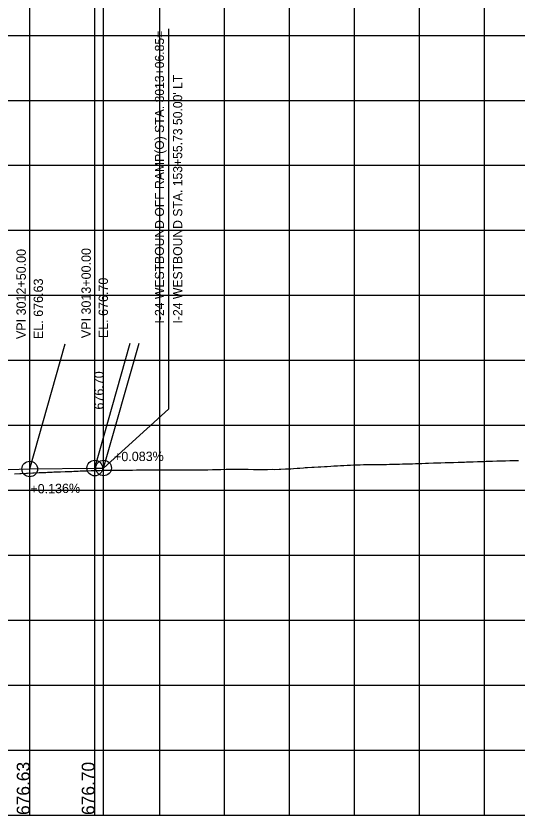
# Model space of a CAD drawing. Extents: x -7164 to 2214450, y -19642 to 253469.
# Drawn here: x 1239 to 1625, y 9000 to 9615 of the extents above; entities that cross this region are included whole.
import ezdxf

# ---------------------------------------------------------------- set-up
doc = ezdxf.new("R2010")
doc.units = 0
for name, color, linetype in [('DESIGN - PROFILE - Proposed', 7, 'Continuous'), ('DESIGN - PROFILE - Proposed Curve Text', 7, 'Continuous'), ('DESIGN - PROFILE - Proposed Text', 7, 'Continuous'), ('DESIGN - SCRATCH - User 1', 7, 'Continuous'), ('DESIGN - SHEET - Light Grid', 7, 'Continuous'), ('SURVEY - PROFILE - Ground Line with Text', 7, 'Continuous')]:
    doc.layers.add(name, color=color, linetype=linetype)

msp = doc.modelspace()

# ---------------------------------------------------------------- linework, layer by layer
at = {"layer": 'DESIGN - PROFILE - Proposed'}
for p, q in [((1250, 9266.3), (1300, 9266.98)), ((1250, 9266.3), (1300, 9266.98)), ((1300, 9266.98), (1306.85, 9267.04)), ((1300, 9266.98), (1306.85, 9267.04)), ((1200, 9265.21), (1250, 9266.3)), ((1200, 9265.21), (1250, 9266.3))]:
    msp.add_line(p, q, dxfattribs=at)
at = {"layer": 'DESIGN - PROFILE - Proposed Text'}
for p, q in [((1356.85, 9604.92), (1356.85, 9377.3)), ((1356.85, 9604.92), (1356.85, 9377.3)), ((1306.85, 9267.04), (1356.85, 9312.3)), ((1306.85, 9267.04), (1356.85, 9312.3))]:
    msp.add_line(p, q, dxfattribs=at)
msp.add_lwpolyline([(1356.85, 9377.3), (1356.85, 9312.3)], dxfattribs=at)
msp.add_lwpolyline([(1356.85, 9377.3), (1356.85, 9312.3)], dxfattribs=at)
for centre in [(1306.85, 9267.04), (1306.85, 9267.04), (1250, 9266.3), (1250, 9266.3), (1300, 9266.98), (1300, 9266.98)]:
    msp.add_circle(centre, 6, dxfattribs=at)
at = {"layer": 'DESIGN - SCRATCH - User 1'}
for p, q in [((1250, 9266.3), (1277.33, 9362.5)), ((1250, 9266.3), (1277.33, 9362.5)), ((1300, 9266.98), (1327.33, 9363.17)), ((1300, 9266.98), (1327.33, 9363.17)), ((1306.85, 9267.04), (1334.18, 9363.23)), ((1306.85, 9267.04), (1334.18, 9363.23)), ((0, 9000), (2600, 9000)), ((0, 9000), (2600, 9000))]:
    msp.add_line(p, q, dxfattribs=at)
msp.add_lwpolyline([(0, 9000), (1306.85, 9000), (1306.85, 10000)], dxfattribs=at)
msp.add_lwpolyline([(0, 9000), (1306.85, 9000), (1306.85, 10000)], dxfattribs=at)
at = {"layer": 'DESIGN - SHEET - Light Grid'}
for p, q in [((1250, 9000), (1250, 10000)), ((1250, 9000), (1250, 10000)), ((1300, 9000), (1300, 10000)), ((1300, 9000), (1300, 10000)), ((1350, 9000), (1350, 10000)), ((1350, 9000), (1350, 10000)), ((1400, 9000), (1400, 10000)), ((1400, 9000), (1400, 10000)), ((1450, 9000), (1450, 10000)), ((1450, 9000), (1450, 10000)), ((1500, 9000), (1500, 10000)), ((1500, 9000), (1500, 10000)), ((1550, 9000), (1550, 10000)), ((1550, 9000), (1550, 10000)), ((1600, 9000), (1600, 10000)), ((1600, 9000), (1600, 10000)), ((0, 9600), (2600, 9600)), ((0, 9600), (2600, 9600)), ((0, 9550), (2600, 9550)), ((0, 9550), (2600, 9550)), ((0, 9500), (2600, 9500)), ((0, 9500), (2600, 9500)), ((0, 9450), (2600, 9450)), ((0, 9450), (2600, 9450)), ((0, 9400), (2600, 9400)), ((0, 9400), (2600, 9400)), ((0, 9350), (2600, 9350)), ((0, 9350), (2600, 9350)), ((0, 9300), (2600, 9300)), ((0, 9300), (2600, 9300)), ((0, 9250), (2600, 9250)), ((0, 9250), (2600, 9250)), ((0, 9200), (2600, 9200)), ((0, 9200), (2600, 9200)), ((0, 9150), (2600, 9150)), ((0, 9150), (2600, 9150)), ((0, 9100), (2600, 9100)), ((0, 9100), (2600, 9100)), ((0, 9050), (2600, 9050)), ((0, 9050), (2600, 9050)), ((0, 9000), (1600, 9000)), ((0, 9000), (1600, 9000))]:
    msp.add_line(p, q, dxfattribs=at)
at = {"layer": 'SURVEY - PROFILE - Ground Line with Text'}
for points in [[(1438.12, 9266.02), (1441.84, 9266.22), (1443.34, 9266.14), (1446.79, 9266.3), (1447.79, 9266.38), (1450.98, 9266.54), (1452.87, 9266.69), (1455.88, 9266.85), (1457.94, 9267.01), (1460.77, 9267.16), (1461.98, 9267.46), (1463.87, 9267.55), (1466.98, 9267.7), (1468.94, 9267.79), (1471.98, 9267.93), (1474.02, 9268.03), (1476.97, 9268.16), (1478.97, 9268.31), (1481.84, 9268.45), (1484.03, 9268.61), (1486.84, 9268.74), (1489.1, 9268.91), (1491.83, 9269.04), (1494.16, 9269.21), (1496.82, 9269.31), (1499.22, 9269.48), (1501.82, 9269.58), (1504.28, 9269.56), (1506.81, 9269.65), (1509.33, 9269.64), (1511.8, 9269.72), (1514.39, 9269.71), (1516.8, 9269.79), (1519.45, 9269.77), (1521.79, 9269.85), (1524.5, 9269.83), (1526.79, 9269.88), (1529.53, 9269.94), (1531.79, 9269.99), (1534.56, 9270.04), (1536.79, 9270.14), (1539.57, 9270.19), (1541.79, 9270.29), (1544.59, 9270.34), (1546.78, 9270.44), (1549.6, 9270.49), (1551.78, 9270.58), (1554.6, 9270.73), (1556.76, 9270.82), (1560.73, 9270.98), (1562.4, 9271.05), (1564.64, 9271.09), (1566.27, 9271.16), (1569.69, 9271.22), (1571.26, 9271.28), (1574.74, 9271.34), (1576.24, 9271.4), (1579.79, 9271.46), (1581.23, 9271.52), (1584.7, 9271.65), (1586.19, 9271.7), (1589.65, 9271.83), (1591.21, 9271.88), (1594.6, 9272), (1596.22, 9272.06), (1599.56, 9272.18), (1601.23, 9272.23), (1604.52, 9272.35), (1606.23, 9272.4), (1609.49, 9272.47), (1611.24, 9272.53), (1614.47, 9272.6), (1616.25, 9272.65), (1619.44, 9272.72), (1621.25, 9272.77), (1624.42, 9272.84), (1626.26, 9272.89)], [(1438.12, 9266.02), (1441.84, 9266.22), (1443.34, 9266.14), (1446.79, 9266.3), (1447.79, 9266.38), (1450.98, 9266.54), (1452.87, 9266.69), (1455.88, 9266.85), (1457.94, 9267.01), (1460.77, 9267.16), (1461.98, 9267.46), (1463.87, 9267.55), (1466.98, 9267.7), (1468.94, 9267.79), (1471.98, 9267.93), (1474.02, 9268.03), (1476.97, 9268.16), (1478.97, 9268.31), (1481.84, 9268.45), (1484.03, 9268.61), (1486.84, 9268.74), (1489.1, 9268.91), (1491.83, 9269.04), (1494.16, 9269.21), (1496.82, 9269.31), (1499.22, 9269.48), (1501.82, 9269.58), (1504.28, 9269.56), (1506.81, 9269.65), (1509.33, 9269.64), (1511.8, 9269.72), (1514.39, 9269.71), (1516.8, 9269.79), (1519.45, 9269.77), (1521.79, 9269.85), (1524.5, 9269.83), (1526.79, 9269.88), (1529.53, 9269.94), (1531.79, 9269.99), (1534.56, 9270.04), (1536.79, 9270.14), (1539.57, 9270.19), (1541.79, 9270.29), (1544.59, 9270.34), (1546.78, 9270.44), (1549.6, 9270.49), (1551.78, 9270.58), (1554.6, 9270.73), (1556.76, 9270.82), (1560.73, 9270.98), (1562.4, 9271.05), (1564.64, 9271.09), (1566.27, 9271.16), (1569.69, 9271.22), (1571.26, 9271.28), (1574.74, 9271.34), (1576.24, 9271.4), (1579.79, 9271.46), (1581.23, 9271.52), (1584.7, 9271.65), (1586.19, 9271.7), (1589.65, 9271.83), (1591.21, 9271.88), (1594.6, 9272), (1596.22, 9272.06), (1599.56, 9272.18), (1601.23, 9272.23), (1604.52, 9272.35), (1606.23, 9272.4), (1609.49, 9272.47), (1611.24, 9272.53), (1614.47, 9272.6), (1616.25, 9272.65), (1619.44, 9272.72), (1621.25, 9272.77), (1624.42, 9272.84), (1626.26, 9272.89)], [(1238.31, 9262.6), (1242.42, 9262.76), (1243.35, 9262.85), (1247.41, 9263), (1248.4, 9263.09), (1252.39, 9263.23), (1253.46, 9263.34), (1257.37, 9263.48), (1258.52, 9263.59), (1262.35, 9263.72), (1263.59, 9263.85), (1267.34, 9263.89), (1268.65, 9264.03), (1272.32, 9264.07), (1273.73, 9264.21), (1277.31, 9264.25), (1278.81, 9264.4), (1282.29, 9264.44), (1283.9, 9264.6), (1287.28, 9264.66), (1288.9, 9264.82), (1292.27, 9264.87), (1293.91, 9264.96), (1297.27, 9265.01), (1298.92, 9265.1), (1302.26, 9265.14), (1303.95, 9265.24), (1306.85, 9265.27), (1307.26, 9265.27), (1308.99, 9265.37), (1312.25, 9265.41), (1314.04, 9265.39), (1317.24, 9265.43), (1319.09, 9265.41), (1322.24, 9265.44), (1324.15, 9265.45), (1327.23, 9265.48), (1329.21, 9265.5), (1332.23, 9265.53), (1334.27, 9265.54), (1337.23, 9265.57), (1339.35, 9265.58), (1342.22, 9265.61), (1344.42, 9265.6), (1347.22, 9265.63), (1349.51, 9265.61), (1352.21, 9265.64), (1354.61, 9265.62), (1357.21, 9265.62), (1359.71, 9265.6), (1362.2, 9265.59), (1364.83, 9265.57), (1367.19, 9265.57), (1369.96, 9265.55), (1372.19, 9265.54), (1375.1, 9265.59), (1377.18, 9265.59), (1380.26, 9265.64), (1382.18, 9265.64), (1385.45, 9265.7), (1387.17, 9265.76), (1390.65, 9265.83), (1392.16, 9265.88), (1395.89, 9265.94), (1397.15, 9265.98), (1401.17, 9266.05), (1402.14, 9266.08), (1406.44, 9266.11), (1407.14, 9266.13), (1411.75, 9266.15), (1412.13, 9266.16), (1417.06, 9266.07), (1417.13, 9266.08), (1418.15, 9266.05), (1422.08, 9266.02), (1422.35, 9266.01), (1427, 9265.96), (1427.63, 9265.93), (1431.94, 9265.88), (1432.91, 9265.83), (1436.89, 9266.08), (1438.12, 9266.02)], [(1238.31, 9262.6), (1242.42, 9262.76), (1243.35, 9262.85), (1247.41, 9263), (1248.4, 9263.09), (1252.39, 9263.23), (1253.46, 9263.34), (1257.37, 9263.48), (1258.52, 9263.59), (1262.35, 9263.72), (1263.59, 9263.85), (1267.34, 9263.89), (1268.65, 9264.03), (1272.32, 9264.07), (1273.73, 9264.21), (1277.31, 9264.25), (1278.81, 9264.4), (1282.29, 9264.44), (1283.9, 9264.6), (1287.28, 9264.66), (1288.9, 9264.82), (1292.27, 9264.87), (1293.91, 9264.96), (1297.27, 9265.01), (1298.92, 9265.1), (1302.26, 9265.14), (1303.95, 9265.24), (1306.85, 9265.27), (1307.26, 9265.27), (1308.99, 9265.37), (1312.25, 9265.41), (1314.04, 9265.39), (1317.24, 9265.43), (1319.09, 9265.41), (1322.24, 9265.44), (1324.15, 9265.45), (1327.23, 9265.48), (1329.21, 9265.5), (1332.23, 9265.53), (1334.27, 9265.54), (1337.23, 9265.57), (1339.35, 9265.58), (1342.22, 9265.61), (1344.42, 9265.6), (1347.22, 9265.63), (1349.51, 9265.61), (1352.21, 9265.64), (1354.61, 9265.62), (1357.21, 9265.62), (1359.71, 9265.6), (1362.2, 9265.59), (1364.83, 9265.57), (1367.19, 9265.57), (1369.96, 9265.55), (1372.19, 9265.54), (1375.1, 9265.59), (1377.18, 9265.59), (1380.26, 9265.64), (1382.18, 9265.64), (1385.45, 9265.7), (1387.17, 9265.76), (1390.65, 9265.83), (1392.16, 9265.88), (1395.89, 9265.94), (1397.15, 9265.98), (1401.17, 9266.05), (1402.14, 9266.08), (1406.44, 9266.11), (1407.14, 9266.13), (1411.75, 9266.15), (1412.13, 9266.16), (1417.06, 9266.07), (1417.13, 9266.08), (1418.15, 9266.05), (1422.08, 9266.02), (1422.35, 9266.01), (1427, 9265.96), (1427.63, 9265.93), (1431.94, 9265.88), (1432.91, 9265.83), (1436.89, 9266.08), (1438.12, 9266.02)]]:
    msp.add_lwpolyline(points, dxfattribs=at)

# ---------------------------------------------------------------- texts
at = {"layer": 'DESIGN - PROFILE - Proposed Curve Text'}
for s, p in [('VPI 3012+50.00', (1247, 9366.3)), ('VPI 3012+50.00', (1247, 9366.3)), ('VPI 3013+00.00', (1297, 9366.98)), ('VPI 3013+00.00', (1297, 9366.98)), ('EL. 676.63', (1260.2, 9366.3)), ('EL. 676.63', (1260.2, 9366.3)), ('EL. 676.70', (1310.2, 9366.98)), ('EL. 676.70', (1310.2, 9366.98)), ('676.70', (1306.85, 9312.04)), ('676.70', (1306.85, 9312.04))]:
    msp.add_text(s, height=7.2, rotation=90, dxfattribs=at).set_placement(p)
at = {"layer": 'DESIGN - PROFILE - Proposed Text'}
for s, height, rotation, p in [('I-24 WESTBOUND OFF RAMP(O) STA. 3013+06.85=', 7, 90, (1353.35, 9378.3)), ('I-24 WESTBOUND OFF RAMP(O) STA. 3013+06.85=', 7, 90, (1353.35, 9378.3)), ("I-24 WESTBOUND STA. 153+55.73 50.00' LT", 7, 90, (1367.35, 9378.3)), ('I-24 WESTBOUND STA. 153+55.73', 7, 90, (1367.35, 9378.3)), ('+0.083%', 7.2, 0.47676, (1314.91, 9272.23)), ('+0.083%', 7.2, 0.47676, (1314.91, 9272.23)), ('+0.136%', 7.2, 0.77803, (1250.54, 9247.42)), ('+0.136%', 7.2, 0.77803, (1250.54, 9247.42)), ('676.63', 10, 90, (1250, 9000)), ('676.63', 10, 90, (1250, 9000)), ('676.70', 10, 90, (1300, 9000)), ('676.70', 10, 90, (1300, 9000))]:
    msp.add_text(s, height=height, rotation=rotation, dxfattribs=at).set_placement(p)

doc.saveas('drawing.dxf')
